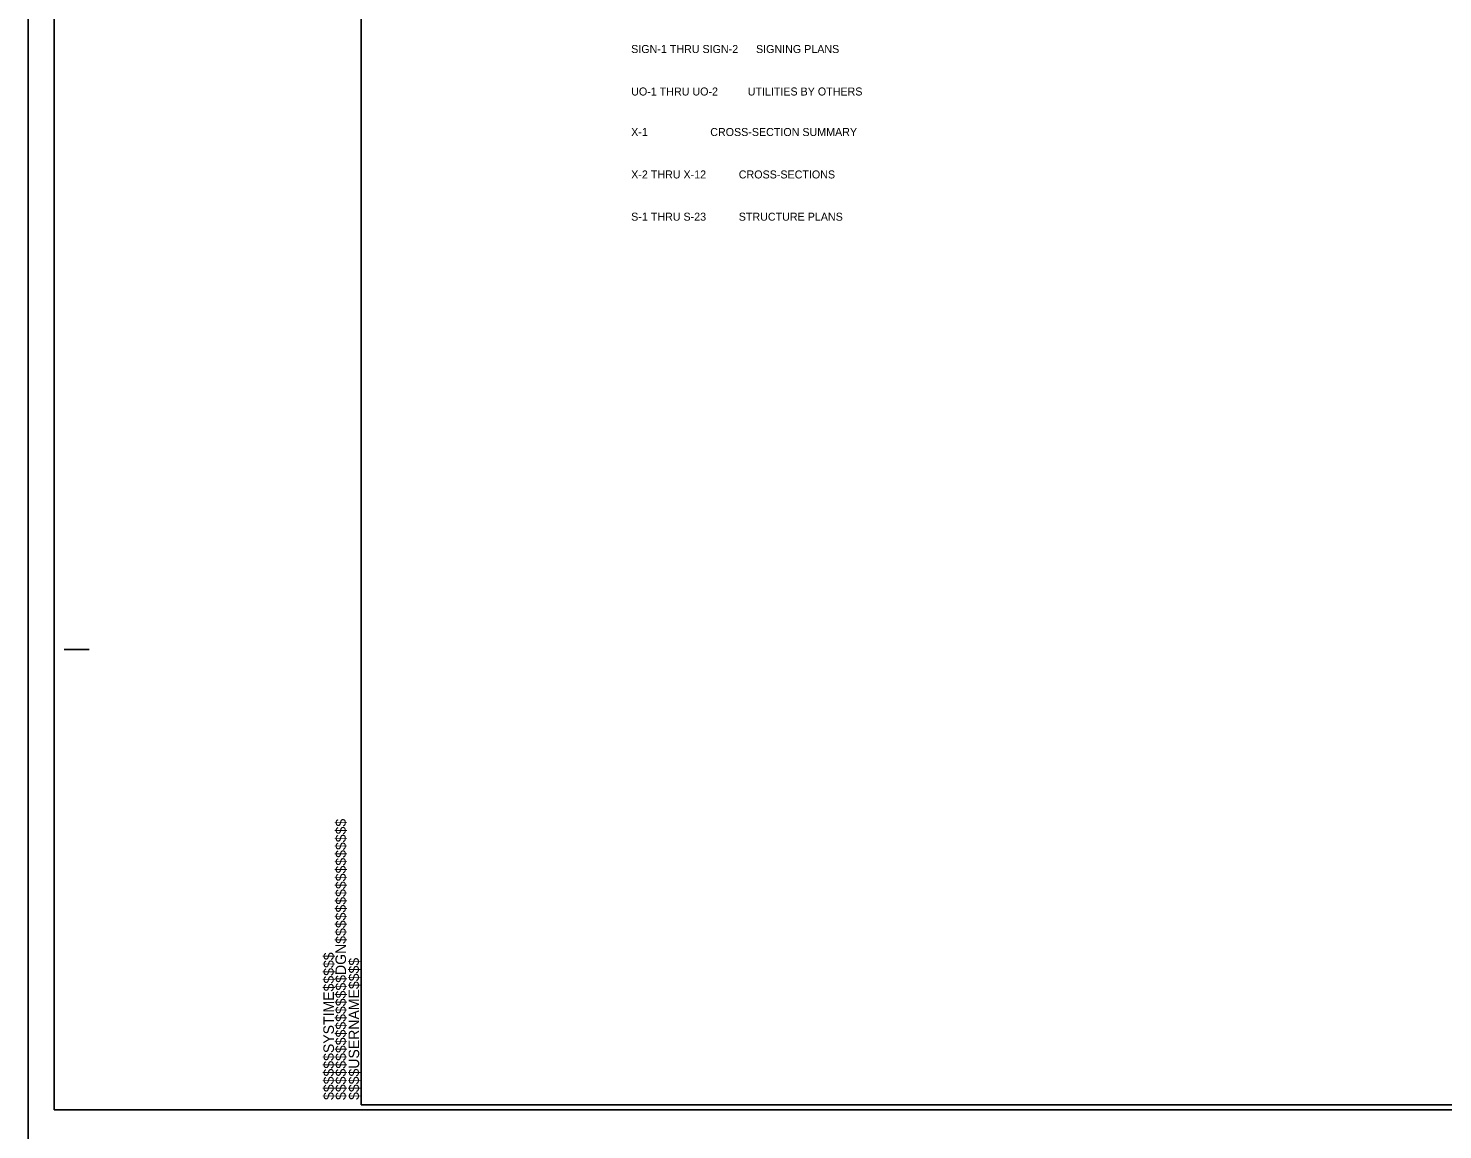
# Model space of a CAD drawing. Extents: x 1974126 to 1975810, y 438878 to 442173.
# Drawn here: x 1974126 to 1974833, y 441088 to 441639 of the extents above; entities that cross this region are included whole.
import ezdxf

# ---------------------------------------------------------------- set-up
doc = ezdxf.new("R2010")
doc.units = 0
for name, color, linetype in [('Sheet Cutting Line CELL', 7, 'Continuous'), ('Sheet Data Text CELL', 7, 'Continuous'), ('Sheet Plan CELL', 7, 'Continuous'), ('Sheet Plot Border Inside CELL', 7, 'Continuous'), ('Sheet Plot Border Outside CELL', 7, 'Continuous')]:
    doc.layers.add(name, color=color, linetype=linetype)

msp = doc.modelspace()

# ---------------------------------------------------------------- linework, layer by layer
at = {"layer": 'Sheet Cutting Line CELL'}
msp.add_line((1974125.64, 442173.29), (1974125.64, 441078.29), dxfattribs=at)
at = {"layer": 'Sheet Plan CELL'}
for p, q in [((1974143.64, 441328.29), (1974156.14, 441328.29)), ((1974292.14, 441100.79), (1974292.14, 441100.79))]:
    msp.add_line(p, q, dxfattribs=at)
msp.add_lwpolyline([(1975792.14, 442150.79), (1974292.14, 442150.79), (1974292.14, 441100.79), (1975792.14, 441100.79)], close=True, dxfattribs=at)
at = {"layer": 'Sheet Plot Border Inside CELL'}
msp.add_lwpolyline([(1974138.64, 441098.29), (1975804.64, 441098.29), (1975804.64, 442153.29), (1974138.64, 442153.29)], close=True, dxfattribs=at)
at = {"layer": 'Sheet Plot Border Outside CELL'}
msp.add_lwpolyline([(1974125.64, 441078.29), (1975809.14, 441078.29), (1975809.14, 442173.29), (1974125.64, 442173.29)], close=True, dxfattribs=at)

# ---------------------------------------------------------------- texts
at = {"layer": 'Sheet Data Text CELL'}
for s, p in [('SIGN-1 THRU SIGN-2      SIGNING PLANS', (1974427.08, 441626.49)), ('UO-1 THRU UO-2          UTILITIES BY OTHERS', (1974427.08, 441605.26)), ('X-1                     CROSS-SECTION SUMMARY', (1974427.08, 441585.01)), ('X-2 THRU X-12           CROSS-SECTIONS', (1974427.08, 441563.8)), ('S-1 THRU S-23           STRUCTURE PLANS', (1974427.08, 441542.68))]:
    msp.add_text(s, height=4, dxfattribs=at).set_placement(p)
at = {"layer": 'Sheet Plan CELL'}
for s, p in [('$$$$$$$$$$$$$$$$DGN$$$$$$$$$$$$$$$$', (1974284.49, 441103.16)), ('$$$$$$SYSTIME$$$$$', (1974278.44, 441103.16)), ('$$$$USERNAME$$$$', (1974291.07, 441103.17))]:
    msp.add_text(s, height=5.25, rotation=90, dxfattribs=at).set_placement(p)

doc.saveas('drawing.dxf')
